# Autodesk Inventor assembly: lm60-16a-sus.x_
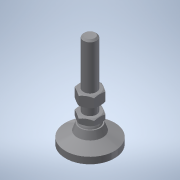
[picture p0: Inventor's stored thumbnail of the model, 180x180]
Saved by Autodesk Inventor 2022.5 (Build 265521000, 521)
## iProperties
Part Number: lm60-16a-sus.x_
Material: 一般
Document SubType Name: Assembly
Designer: ImaoCorp
Sending System: SOLIDWORKS 2017-2017317
MC: AMD64
MC_MODEL: Intel64 Family 6 Model 60 Stepping 3, GenuineIntel
OS: Windows_NT
FRU: Parasolid Version 29.0, build 201,  4-17-2017
FORMAT: text
GUISE: transmit
KEY: lm60-16a-sus
FILE: lm60-16a-sus.x_t
DATE: Mon Jul 01 17:51:27 2019
Author: ImaoCorp
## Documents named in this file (3)
- X:\14_SW2022-Inv2022\00_全2023-1023新製品(TCC)まで\l\lm60-16a-sus\LM60-16A-SUS.iam
- X:\14_SW2022-Inv2022\00_全2023-1023新製品(TCC)まで\l\lm60-16a-sus\lm60-16a-sus_01.ipt
- X:\14_SW2022-Inv2022\00_全2023-1023新製品(TCC)まで\l\lm60-16a-sus\lm60-16a-sus_02.ipt
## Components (2 placed, 2 different names)
1. lm60-16a-sus_01
2. lm60-16a-sus_02
